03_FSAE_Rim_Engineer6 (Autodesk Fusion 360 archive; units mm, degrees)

design "03 FSAE Rim - Engineer 6" references "Hexagon Nut DIN 934 - M4 x 0.7 Steel 6 Plain", "Hexagon Socket Head Cap Screw DIN 912 - M4 x 0.7 x 16 Steel 4.6 Plain"
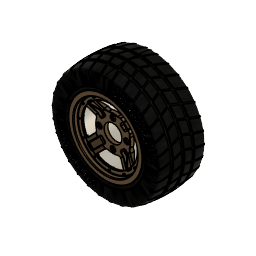
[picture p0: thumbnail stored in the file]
part number: 2026-07-27-09-56-27-671
part number: 2026-08-04-10-59-52-273
part number: 2026-08-04-10-59-52-284
part number: 2026-08-04-10-59-52-289
sketch "Sketch1" plane through (0, 0, 0) normal (1, 0, 0) x axis (0, 1, 0)
  line L1 (153.5, 0) -> (0, 0)
  line L2 (0, 119.5) -> (0, 104)
  line L3 (143.5, 124.5) -> (5, 124.5)
  line L4 (148.5, 134.75) -> (148.5, 129.5)
  line L5 (153.5, 138.25) -> (152, 138.25)
  line L6 (2.5, 119.5) -> (2.5, 104)
  line L7 (143.5, 122) -> (5, 122)
  line L8 (151, 134.75) -> (151, 129.5)
  line L9 (153.5, 135.75) -> (152, 135.75)
  line L10 (2.5, 104) -> (0, 104)
  line L11 (153.5, 135.75) -> (153.5, 138.25)
  arc A1 centre (152, 134.75) radius 3.5 clockwise from (148.5, 134.75) to (152, 138.25)
  arc A2 centre (143.5, 129.5) radius 5 clockwise from (148.5, 129.5) to (143.5, 124.5)
  arc A3 centre (5, 119.5) radius 5 clockwise from (0, 119.5) to (5, 124.5)
  arc A4 centre (5, 119.5) radius 2.5 clockwise from (2.5, 119.5) to (5, 122)
  arc A5 centre (143.5, 129.5) radius 7.5 clockwise from (151, 129.5) to (143.5, 122)
  arc A6 centre (152, 134.75) radius 1 clockwise from (151, 134.75) to (152, 135.75)
  point P1 (0, 0)
  point P2 (0, 0)
  point P4 (0, 104)
  point P3 (153.5, 0)
  point P7 (153.5, 138.25)
  point P6 (148.5, 124.5)
  point P5 (0, 124.5)
  coincident P1 P2
  horizontal L1
  perpendicular L1 L2
  perpendicular L2 L3
  perpendicular L3 L4
  perpendicular L4 L5
  vertical P1 P4
  vertical P3 P7
  tangent L4 A1
  tangent L5 A1
  coincident P6 L3
  coincident P6 L4
  tangent L3 A2
  tangent L4 A2
  coincident P5 L2
  coincident P5 L3
  tangent L2 A3
  tangent L3 A3
  equal A2 A3
  perpendicular L6 L10
  perpendicular L9 L11
  dimension "d1" distance P2 P3 = 153.5
  dimension "d2" = 208
  dimension "d3" = 249
  dimension "d4" = 276.5
  dimension "d5" distance P5 P6 = 148.5
  dimension "d6" radius A1 = 3.5
  dimension "d7" radius A2 = 5
  dimension "d8" = 2.5
revolve "Revolve1" sketch "Sketch1" AlongAngle 360 bodies "FSAE Rim Back"
sketch "Sketch2" plane through (0, 0, 0) normal (0, -1, 0) x axis (1, 0, 0)
  circle C1 centre (0, 0) radius 104
  circle C2 centre (0, 0) radius 119.5
  circle C3 centre (0, 0) radius 112
  circle C4 centre (0, 112) radius 2.15
  point P1 (0, 0)
  point P3 (0, 0)
  point P4 (0, 112)
  coincident P1 P3
  coincident C3 P4
  vertical P3 P4
  dimension "d10" diameter C3 = 224
  dimension "d11" diameter C4 = 4.3
extrude "Extrude1" cut sketch "Sketch2" profile of C4 to an object
circular_pattern "C-Pattern1" TotalAngle 360
canvas "Canvas1"
move "Move1"
sketch "Sketch4" plane through (0, 0, 0) normal (1, 0, 0) x axis (0, 1, 0)
  line L1 (14, 0) -> (0, 0)
  line L2 (14, 72.5) -> (14, 0)
  line L3 (-8, 102.5) -> (14, 72.5)
  line L4 (-8, 124.5) -> (-8, 102.5)
  line L5 (-23.5, 124.5) -> (-8, 124.5)
  line L6 (-23.5, 138) -> (-23.5, 124.5)
  line L7 (-28.25, 138) -> (-23.5, 138)
  line L8 (-28.25, 0) -> (-28.25, 138)
  line L9 (0, 0) -> (-28.25, 0)
  line L10 (-13, 118.1658) -> (-28.25, 119.5)
  line L11 (-13, 102.5) -> (-13, 118.1658)
  line L12 (0, 68.6338) -> (-13, 102.5)
  line L13 (0, 0) -> (0, 68.6338)
  point P1 (0, 0)
  point P2 (0, 0)
  point P11 (0, 0)
  point P12 (-28.25, 119.5)
  point P5 (-8, 102.5)
  point P14 (-13, 102.5)
  point P3 (14, 0)
  point P4 (14, 72.5)
  point P6 (-8, 124.5)
  point P8 (-23.5, 138)
  point P9 (-28.25, 138)
  coincident P1 P2
  horizontal L1
  perpendicular L1 L2
  perpendicular L1 L4
  perpendicular L4 L5
  perpendicular L5 L6
  perpendicular L6 L7
  coincident P1 P11
  collinear L1 L9
  perpendicular L8 L9
  coincident L8 P12
  parallel L8 L11
  vertical L13
  horizontal P5 P14
  dimension "d29" distance P2 P3 = 14
  dimension "d30" = 145
  dimension "d31" = 205
  dimension "d32" = 249
  dimension "d33" = 276
  dimension "d34" distance P4 P6 = 22
  dimension "d35" distance P6 P8 = 15.5
  dimension "d36" distance P8 P9 = 4.75
  dimension "d37" distance L4 L11 = 5
  dimension "d38" angle L12 L13 = 159
  dimension "d39" angle L10 L11 = 95
  dimension "d40" = 239
revolve "Revolve3" sketch "Sketch4" AlongAngle 360 bodies "FSAE Rim Front"
sketch "Sketch5" plane through (0, 0, 0) normal (0, -1, 0) x axis (1, 0, 0)
  circle C1 centre (0, 0) radius 68.6338
  circle C2 centre (0, 0) radius 33
  point P1 (0, 0)
  point P3 (0, 0)
  coincident P1 P3
  dimension "d42" diameter C2 = 66
extrude "Extrude2" cut sketch "Sketch5" profile of C2 to an object
sketch "Sketch6" plane through (0, 0, 0) normal (0, -1, 0) x axis (1, 0, 0)
  circle C1 centre (0, 0) radius 33
  circle C2 centre (0, 0) radius 68.6338
  circle C3 centre (0, 0) radius 50.8
  point P1 (0, 0)
  point P4 (0, 0)
  point P3 (0, 50.8)
  coincident P1 P4
  coincident P3 C3
  vertical P1 P3
  dimension "d45" diameter C3 = 101.6
hole "Hole1" HoleDiameter 10.5 TipAngle 180 CBDepth 5 CBDiameter 20
chamfer "Chamfer2" sketch "Sketch1" distance 0.5
circular_pattern "C-Pattern2" TotalAngle 360
sketch "Sketch7" plane through (0, -13, 0) normal (0, -1, 0) x axis (1, 0, 0)
  circle C1 centre (0, 0) radius 102.5
  circle C2 centre (0, 0) radius 118.1658
  circle C3 centre (0, 0) radius 112
  point P1 (0, 0)
  point P3 (0, 0)
  point P4 (0, 112)
  coincident P1 P3
  coincident C3 P4
  vertical P1 P4
  dimension "d53" diameter C3 = 224
hole "Hole2" HoleDiameter 4.3 TipAngle 180
circular_pattern "C-Pattern3" TotalAngle 360
fillet "Fillet1" radius 1 3 2
chamfer "Chamfer1" distance 0.5
form "Form1" bodies "Tire"
fillet "Fillet2" radius 5
sketch "Sketch8" plane through (0, 0, 0) normal (1, 0, 0) x axis (0, 1, 0)
  line L1 (47.5, 224.911) -> (47.5, 204.911)
  line L2 (57.5, 224.911) -> (47.5, 224.911)
  line L3 (57.5, 204.9943) -> (57.5, 224.911)
  line L4 (87.5, 224.911) -> (87.5, 204.2438)
  line L5 (97.5, 224.911) -> (87.5, 224.911)
  line L6 (97.5, 203.6595) -> (97.5, 224.911)
  line L7 (17.5, 224.911) -> (17.5, 203.6595)
  line L8 (7.5, 224.911) -> (17.5, 224.911)
  line L9 (7.5, 202.9073) -> (7.5, 224.911)
  arc A1 centre (57.5, -395.0057) radius 600 clockwise from (-46, 196) to (161, 196)
  point P2 (-46, 196)
  point P3 (161, 196)
  point P8 (57.5, 204.9943)
  point P9 (87.5, 204.2438)
  point P12 (97.5, 203.6595)
  point P13 (17.5, 203.6595)
  point P16 (7.5, 202.9073)
  point P5 (47.5, 204.911)
  point P1 (0, 0)
  point P6 (47.5, 224.911)
  point P7 (57.5, 224.911)
  horizontal P2 P3
  vertical L1
  perpendicular L1 L2
  midpoint A1 P8
  perpendicular L2 L3
  coincident A1 P9
  parallel L3 L4
  perpendicular L4 L5
  coincident A1 P12
  perpendicular L5 L6
  coincident A1 P13
  perpendicular L5 L7
  perpendicular L7 L8
  coincident A1 P16
  perpendicular L8 L9
  collinear L2 L8
  collinear L2 L5
  equal L2 L8
  equal L2 L5
  coincident A1 P5
  dimension "d68" radius A1 = 600
  dimension "d69" distance P1 P3 = 196
  dimension "d70" distance P1 P2 = 46
  dimension "d71" distance P1 P3 = 161
  dimension "d73" distance P6 P7 = 10
  dimension "d74" distance L1 L7 = 30
  dimension "d75" distance L3 L4 = 30
  dimension "d76" distance P5 P6 = 20
revolve "Revolve4" AlongAngle 360
revolve "Revolve5" sketch "Sketch8" AlongAngle 360
work_plane "WorkPlane1" AlongDistance 275 ExtraOffset 0
sketch "Sketch9" plane through (0, 0, 275) normal (0, 0, 1) x axis (1, 0, 0)
  line L1 (-48.7008, 53.5011) -> (0, -75.7953)
  line L2 (0, 197.5142) -> (-48.7008, 53.5011)
  line L3 (-43.392, 53.5917) -> (4.6791, -74.0329)
  line L4 (4.7365, 195.9124) -> (-43.392, 53.5917)
  line L5 (4.6791, -74.0329) -> (0, -75.7953)
  line L6 (0, 197.5142) -> (4.7365, 195.9124)
  perpendicular L3 L5
  perpendicular L2 L6
  dimension "d80" = 5
step "SurfaceExtend" extendDistance 125
extrude "Extrude3" cut sketch "Sketch9" to an object
circular_pattern "C-Pattern4" countU 30 TotalAngle 360
remove_body "RemoveBody1"
remove_body "RemoveBody2"
work_plane "WorkPlane2" AlongDistance -150 ExtraOffset 0
sketch "Sketch10" plane through (0, -150, 0) normal (0, 1, 0) x axis (1, 0, 0)
  circle C1 centre (0, 0) radius 157.5
  point P1 (0, 0)
  point P2 (0, 0)
  coincident P1 P2
  dimension "d88" diameter C1 = 315
  dimension "d89" Text1-Height = 20
extrude "Extrude4" sketch "Sketch10" blind 2
circular_pattern "C-Pattern5" TotalAngle 360
component_from_bodies "Body->Comp1"
component_from_bodies "Body->Comp2"
component_from_bodies "Body->Comp3"
sketch "Sketch1" plane through (0, -13, 0) normal (0, -1, 0) x axis (1, 0, 0)
  line L1 (0, 103.056) -> (0, 0)
  line L2 (103.056, 0) -> (0, 0)
  line L3 (72.8716, 72.8716) -> (0, 0)
  line L4 (88.3726, 53.0172) -> (60.1041, 24.7487)
  line L5 (53.0172, 88.3726) -> (24.7487, 60.1041)
  circle C1 centre (0, 0) radius 103.056
  circle C2 centre (0, 112) radius 2.15
  circle C3 centre (56, 96.9948) radius 2.15
  circle C4 centre (96.9948, 56) radius 2.15
  circle C5 centre (112, 0) radius 2.15
  circle C6 centre (96.9948, -56) radius 2.15
  circle C7 centre (56, -96.9948) radius 2.15
  circle C8 centre (0, -112) radius 2.15
  circle C9 centre (-56, -96.9948) radius 2.15
  circle C10 centre (-96.9948, -56) radius 2.15
  circle C11 centre (-112, 0) radius 2.15
  circle C12 centre (-96.9948, 56) radius 2.15
  circle C13 centre (-56, 96.9948) radius 2.15
  circle C14 centre (0, 0) radius 116.3331
  arc A1 centre (0, 0) radius 65 clockwise from (0, 65) to (65, 0)
  arc A2 centre (0, 0) radius 65 clockwise from (65, 0) to (0, 65)
  point P2 (0, 0)
  point P16 (0, 0)
  point P17 (0, 103.056)
  point P18 (103.056, 0)
  point P15 (0, 0)
  point P19 (0, 0)
  point P20 (72.8716, 72.8716)
  point P22 (24.7487, 60.1041)
  point P21 (60.1041, 24.7487)
  point P23 (53.0172, 88.3726)
  point P24 (88.3726, 53.0172)
  point P25 (0, 65)
  point P26 (65, 0)
  concentric C1 A1
  coincident P2 P16
  coincident C1 P17
  vertical L1
  coincident C1 P18
  perpendicular L1 L2
  coincident P15 P19
  coincident C1 P20
  coincident P22 A1
  coincident P21 A1
  coincident C1 P23
  coincident C1 P24
  coincident L1 P25
  coincident L2 P26
  concentric A1 A2
  dimension "d95" diameter A1 = 130
  dimension "d96" angle L1 L3 = 45
extrude "Extrude1" cut sketch "Sketch1" profile of C1 L1 L2 L4 L5 A1 to an object
circular_pattern "C-Pattern1" TotalAngle 360
sketch "Sketch2" plane through (0, -13, 0) normal (0, -1, 0) x axis (1, 0, 0)
  line L1 (72.8716, 72.8716) -> (0, 0)
  line L2 (65.9862, 82.9568) -> (25.8367, 42.8073)
  line L3 (82.9568, 65.9862) -> (42.8073, 25.8367)
  arc A1 centre (0, 0) radius 103.056 clockwise from (-53.0172, 88.3726) to (53.0172, 88.3726)
  arc A2 centre (0, 0) radius 103.056 clockwise from (53.0172, 88.3726) to (88.3726, 53.0172)
  arc A3 centre (0, 0) radius 103.056 clockwise from (88.3726, 53.0172) to (88.3726, -53.0172)
  arc A4 centre (0, 0) radius 103.056 clockwise from (88.3726, -53.0172) to (53.0172, -88.3726)
  arc A5 centre (0, 0) radius 103.056 clockwise from (53.0172, -88.3726) to (-53.0172, -88.3726)
  arc A6 centre (0, 0) radius 103.056 clockwise from (-53.0172, -88.3726) to (-88.3726, -53.0172)
  arc A7 centre (0, 0) radius 103.056 clockwise from (-88.3726, -53.0172) to (-88.3726, 53.0172)
  arc A8 centre (0, 0) radius 103.056 clockwise from (-88.3726, 53.0172) to (-53.0172, 88.3726)
  circle C1 centre (0, 112) radius 2.15
  circle C2 centre (56, 96.9948) radius 2.15
  circle C3 centre (96.9948, 56) radius 2.15
  circle C4 centre (112, 0) radius 2.15
  circle C5 centre (96.9948, -56) radius 2.15
  circle C6 centre (56, -96.9948) radius 2.15
  circle C7 centre (0, -112) radius 2.15
  circle C8 centre (-56, -96.9948) radius 2.15
  circle C9 centre (-96.9948, -56) radius 2.15
  circle C10 centre (-112, 0) radius 2.15
  circle C11 centre (-96.9948, 56) radius 2.15
  circle C12 centre (-56, 96.9948) radius 2.15
  circle C13 centre (0, 0) radius 116.3331
  circle C14 centre (0, 0) radius 50
  circle C15 centre (0, 0) radius 106
  point P23 (0, 0)
  point P25 (0, 0)
  point P27 (25.8367, 42.8073)
  point P28 (42.8073, 25.8367)
  point P29 (82.9568, 65.9862)
  point P30 (65.9862, 82.9568)
  parallel L1 L2
  parallel L1 L3
  coincident P23 P25
  concentric C14 C15
  coincident C14 P27
  coincident C14 P28
  coincident C15 P29
  coincident C15 P30
  dimension "d103" distance L1 L2 = 12
  dimension "d104" distance L1 L3 = 12 (= "d103")
  dimension "d105" diameter C14 = 100
  dimension "d106" diameter C15 = 212
extrude "Extrude2" cut sketch "Sketch2" profile of A2 L2 L3 C14 C15 to an object offset 2
fillet "Fillet1" radius 5
fillet "Fillet2" radius 10
fillet "Fillet3" radius 2
circular_pattern "C-Pattern2" TotalAngle 360
fillet "Fillet4" radius 15 5
chamfer "Chamfer1" sketch "Sketch1" distance 1
step "Screw1"
joint "Assemble" alignAngle 0 alignOffsetX 0 alignOffsetY 0 alignOffsetZ 0
step "Screw2"
joint "Assemble" alignAngle 0 alignOffsetX 0 alignOffsetY 0 alignOffsetZ 0
step "Screw3"
joint "Assemble" alignAngle 0 alignOffsetX 0 alignOffsetY 0 alignOffsetZ 0
step "Screw4"
joint "Assemble" alignAngle 0 alignOffsetX 0 alignOffsetY 0 alignOffsetZ 0
step "Screw5"
joint "Assemble" alignAngle 0 alignOffsetX 0 alignOffsetY 0 alignOffsetZ 0
step "Screw6"
joint "Assemble" alignAngle 0 alignOffsetX 0 alignOffsetY 0 alignOffsetZ 0
step "Screw7"
joint "Assemble" alignAngle 0 alignOffsetX 0 alignOffsetY 0 alignOffsetZ 0
step "Screw8"
joint "Assemble" alignAngle 0 alignOffsetX 0 alignOffsetY 0 alignOffsetZ 0
step "Screw9"
joint "Assemble" alignAngle 0 alignOffsetX 0 alignOffsetY 0 alignOffsetZ 0
step "Screw10"
joint "Assemble" alignAngle 0 alignOffsetX 0 alignOffsetY 0 alignOffsetZ 0
step "Screw11"
joint "Assemble" alignAngle 0 alignOffsetX 0 alignOffsetY 0 alignOffsetZ 0
step "Screw12"
joint "Assemble" alignAngle 0 alignOffsetX 0 alignOffsetY 0 alignOffsetZ 0
step "Nut13"
joint "Assemble" alignAngle 0 alignOffsetX 0 alignOffsetY 0 alignOffsetZ 0
step "Nut14"
joint "Assemble" alignAngle 0 alignOffsetX 0 alignOffsetY 0 alignOffsetZ 0
step "Nut15"
joint "Assemble" alignAngle 0 alignOffsetX 0 alignOffsetY 0 alignOffsetZ 0
step "Nut16"
joint "Assemble" alignAngle 0 alignOffsetX 0 alignOffsetY 0 alignOffsetZ 0
step "Nut17"
joint "Assemble" alignAngle 0 alignOffsetX 0 alignOffsetY 0 alignOffsetZ 0
step "Nut18"
joint "Assemble" alignAngle 0 alignOffsetX 0 alignOffsetY 0 alignOffsetZ 0
step "Nut19"
joint "Assemble" alignAngle 0 alignOffsetX 0 alignOffsetY 0 alignOffsetZ 0
step "Nut20"
joint "Assemble" alignAngle 0 alignOffsetX 0 alignOffsetY 0 alignOffsetZ 0
step "Nut21"
joint "Assemble" alignAngle 0 alignOffsetX 0 alignOffsetY 0 alignOffsetZ 0
step "Nut22"
joint "Assemble" alignAngle 0 alignOffsetX 0 alignOffsetY 0 alignOffsetZ 0
step "Nut23"
joint "Assemble" alignAngle 0 alignOffsetX 0 alignOffsetY 0 alignOffsetZ 0
step "Nut24"
joint "Assemble" alignAngle 0 alignOffsetX 0 alignOffsetY 0 alignOffsetZ 0
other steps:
base_feature "Base Feature1" bodies "FSAE Rim Back"
base_feature "Base Feature1" bodies "Tire"
base_feature "Base Feature1" bodies "FSAE Rim Front"
create_component "CreateComponent1"
reparent_decal "ReparentDecal1"
remove_body "RemoveBody3"
create_component "CreateComponent2"
reparent_decal "ReparentDecal2"
remove_body "RemoveBody4"
create_component "CreateComponent3"
reparent_decal "ReparentDecal3"
remove_body "RemoveBody5"
joint_origin "JointOrigin1"
joint_origin "JointOrigin2"
joint_origin "JointOrigin3"
joint_origin "JointOrigin4"
joint_origin "JointOrigin5"
joint_origin "JointOrigin6"
joint_origin "JointOrigin7"
joint_origin "JointOrigin8"
joint_origin "JointOrigin9"
joint_origin "JointOrigin10"
joint_origin "JointOrigin11"
joint_origin "JointOrigin12"
joint_origin "JointOrigin1"
joint_origin "JointOrigin2"
joint_origin "JointOrigin3"
joint_origin "JointOrigin4"
joint_origin "JointOrigin5"
joint_origin "JointOrigin6"
joint_origin "JointOrigin7"
joint_origin "JointOrigin8"
joint_origin "JointOrigin9"
joint_origin "JointOrigin10"
joint_origin "JointOrigin11"
joint_origin "JointOrigin12"
named bodies: "FSAE Rim Back", "FSAE Rim Front", "Tire"

design "Hexagon Nut DIN 934 - M4 x 0.7 Steel 6 Plain"
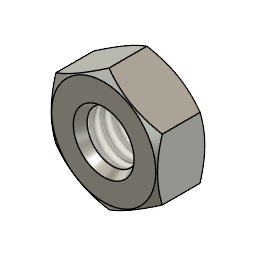
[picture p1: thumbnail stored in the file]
description: Hexagon Nut DIN 934 - M4 x 0.7
part number: DIN 934 - M4 x 0.7 Steel 6 Plain
parameter "adsk_nheig" = 3.2
parameter "adsk_maxdia" = 8.085
parameter "adsk_nomdia" = 4
parameter "adsk_waflat" = 7
parameter "adsk_chamang1" = 30
parameter "adsk_chamang2" = 30
parameter "adsk_beardia" = 6.86 (= "adsk_waflat * 0.98")
sketch "Sketch1" plane through (0, 0, 0) normal (0, 1, 0) x axis (1, 0, 0)
  line L1 (0, -3.2) -> (0, 0)
  line L2 (-3.43, 0) -> (-2, 0)
  line L3 (-4.0425, -0.3536) -> (-3.43, 0)
  line L4 (-4.0425, -2.8464) -> (-4.0425, -0.3536)
  line L5 (-3.43, -3.2) -> (-4.0425, -2.8464)
  line L6 (-2, -3.2) -> (-3.43, -3.2)
  line L7 (-2, 0) -> (-2, -3.2)
  point P3 (0, -3.2)
  point P1 (0, 0)
  point P2 (0, 0)
  point P10 (0, 0)
  point P5 (-3.43, 0)
  point P8 (-3.43, -3.2)
  vertical L1
  coincident L1 P3
  coincident P1 L1
  horizontal L2
  coincident P1 L2
  coincident P2 P10
  coincident P3 L6
  vertical P5 P8
  dimension "d121" = 4 (= "adsk_nomdia")
  dimension "d122" angle L2 L3 = 30 (= "adsk_chamang1")
  dimension "d123" angle L5 L6 = 30 (= "adsk_chamang2")
  dimension "d128" = 8.085 (= "adsk_maxdia")
  dimension "d172" = 6.86 (= "adsk_beardia")
  dimension "d179" distance L2 L6 = 3.2 (= "adsk_nheig")
revolve "Revolve1" sketch "Sketch1" AlongAngle 360
sketch "Sketch8" plane through (0, 0, 3.2) normal (0, 0, 1) x axis (1, 0, 0)
  line L1 (-3.5, 2.0228) -> (-3.5, -2.0228)
  circle C1 centre (0, 0) radius 2
  circle C2 centre (0, 0) radius 4.0425
  point P3 (-3.5, 2.0228)
  point P2 (-3.5, -2.0228)
  point P1 (0, 0)
  coincident P3 C2
  coincident P2 C2
  vertical L1
  dimension "d114" distance P1 L1 = 3.5 (= "adsk_waflat / 2")
extrude "Extrude5" cut sketch "Sketch8" profile of L1 C2 no distance stored
circular_pattern "C-Pattern2" TotalAngle 360
thread "Thread3" ThreadOffset 0 ThreadLength 10
sketch "Sketch12" plane through (0, 0, 0) normal (0, 1, 0) x axis (1, 0, 0)
  line L1 (0, 0) -> (-2, 0)
  line L2 (-2, 0) -> (-1.0762, -1.6)
  line L3 (0, -3.2) -> (-2, -3.2)
  line L4 (-2, -3.2) -> (-1.0762, -1.6)
  line L5 (0, -3.2) -> (0, 0)
  point P4 (-1.0762, -1.6)
  point P7 (-1.0762, -1.6)
  point P2 (-2, 0)
  point P5 (-2, -3.2)
  point P6 (0, -3.2)
  point P9 (0, -3.2)
  point P1 (0, 0)
  point P3 (0, 0)
  horizontal L1
  coincident P4 P7
  vertical P2 P5
  coincident P6 P9
  coincident P1 P3
  perpendicular L3 L5
  dimension "d169" angle L3 L4 = 60
  dimension "d177" distance P2 L5 = 2 (= "adsk_nomdia * 0.5")
  dimension "d178" angle L1 L2 = 60
revolve "Revolve3" sketch "Sketch12" AlongAngle 360
joint_origin "JointOrigin9" OffsetX 0 OffsetY 0 OffsetZ 0 AngleZ 0
joint_origin "JointOrigin10" OffsetX 0 OffsetY 0 OffsetZ 3.2 (= "adsk_nheig") AngleZ 0

design "Hexagon Socket Head Cap Screw DIN 912 - M4 x 0.7 x 16 Steel 4.6 Plain"
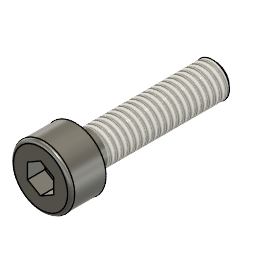
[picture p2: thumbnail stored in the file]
description: Hexagon Socket Head Cap Screw DIN 912 - M4 x 0.7 x 16
part number: DIN 912 - M4 x 0.7 x 16 Steel 4.6 Plain
parameter "adsk_nomlen" = 16
parameter "adsk_headh" = 4
parameter "adsk_headdia" = 7
parameter "adsk_nomdia" = 4
parameter "adsk_philwidth" = 3
parameter "adsk_phildepth" = 2
parameter "adsk_thrlen" = 14.25
parameter "adsk_startlen" = 0.4294
parameter "adsk_endpointdia" = 3.1412
sketch "Sketch1" plane through (0, 0, 0) normal (0, 1, 0) x axis (1, 0, 0)
  line L1 (-2, 16) -> (-2, 0)
  line L2 (0, 16) -> (-2, 16)
  line L3 (0, -4) -> (0, 16)
  line L4 (-3.5, 0) -> (-2, 0)
  line L5 (-3.5, -4) -> (-3.5, 0)
  line L6 (0, -4) -> (-3.5, -4)
  point P1 (0, 0)
  point P4 (0, 16)
  point P7 (0, -4)
  point P5 (-3.5, 0)
  perpendicular L1 L2
  collinear P1 P4 P7
  perpendicular L1 L4
  coincident P1 L4
  vertical L3
  coincident L3 P7
  perpendicular L3 L6
  dimension "d101" distance P1 L2 = 16 (= "adsk_nomlen")
  dimension "d102" distance P5 L6 = 4 (= "adsk_headh")
  dimension "d109" = 7 (= "adsk_headdia")
  dimension "d110" = 4 (= "adsk_nomdia")
revolve "Revolve1" sketch "Sketch1" AlongAngle 360
work_plane "WorkPlane1" AlongDistance 4 (= "adsk_headh")
sketch "Sketch6" plane through (0, 0, 4) normal (0, 0, 1) x axis (1, 0, 0)
  line L1 (1.5, -0.866) -> (0, -1.7321)
  line L2 (1.5, 0.866) -> (1.5, -0.866)
  line L3 (0, 1.7321) -> (1.5, 0.866)
  line L4 (-1.5, 0.866) -> (0, 1.7321)
  line L5 (-1.5, -0.866) -> (-1.5, 0.866)
  line L6 (0, -1.7321) -> (-1.5, -0.866)
  point P1 (0, 0)
  point P8 (0, 0)
  coincident P1 P8
  vertical L2
  dimension "d111" distance L2 L5 = 3 (= "adsk_philwidth")
extrude "Extrude1" cut sketch "Sketch6" no distance stored
extrude "Extrude2" cut of existing geometry no distance stored taper -85
thread "Thread3" ThreadOffset 0 ThreadLength 14.25 (= "min(adsk_thrlen; adsk_nomlen - 0.001 mm)")
fillet "Fillet4" radius 0.4 (= "adsk_nomdia * 0.1")
sketch "Sketch7" plane through (0, 0, 0) normal (0, 1, 0) x axis (1, 0, 0)
  line L1 (-2.04, 15.5706) -> (-2.04, 16)
  line L2 (-1.5706, 16) -> (-2.04, 15.5706)
  line L3 (0, -4) -> (0, 16)
  line L4 (0, 16) -> (-2.04, 16)
  point P5 (0, 16)
  point P7 (0, 16)
  point P4 (-1.5706, 16)
  point P3 (-2.04, 15.5706)
  coincident P5 P7
  perpendicular L3 L4
  coincident P4 L4
  perpendicular L1 L4
  dimension "d104" distance P4 L3 = 1.5706 (= "adsk_endpointdia / 2")
  dimension "d105" distance L1 P7 = 2.04 (= "adsk_nomdia * 0.51")
  dimension "d106" distance P3 L4 = 0.4294 (= "adsk_startlen")
revolve "Revolve3" sketch "Sketch7" AlongAngle 360
joint_origin "JointOrigin2" OffsetX 0 OffsetY 0 OffsetZ 0 AngleZ 0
